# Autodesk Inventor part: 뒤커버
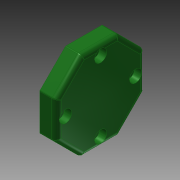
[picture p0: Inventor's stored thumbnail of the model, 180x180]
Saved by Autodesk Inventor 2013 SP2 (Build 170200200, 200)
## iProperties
Created: 2015-11
Part Number: 뒤커버
Material: 알루미늄 6061
Document SubType Name: Modeling
Designer: mduedu
Density: 1 g/cm^3
Author: mduedu
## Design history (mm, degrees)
sketch "스케치5" dims "d66" = 58
  geometry: L1 (12.012, 29)-(29, 12.012); L2 (29, 12.012)-(29, -12.012); L3 (29, -12.012)-(12.012, -29); L4 (12.012, -29)-(-12.012, -29); L5 (-12.012, -29)-(-29, -12.012); L6 (-29, -12.012)-(-29, 12.012); L7 (-29, 12.012)-(-12.012, 29); L8 (-12.012, 29)-(12.012, 29); 4 further points
  constraints: 16 end point, 2 coincident, 2 vertical alignment, 1 midpoint, 19 other
extrude "돌출2" new body sketch "스케치5" distance "d67" = 11; taper "d68" = 0 deg
sketch "스케치6"
  geometry: C1 r 16 at (0, 0); 1 further point
  constraints: 1 centre point, 1 coincident
  dimensions: "d69" = 32 diameter of C1
extrude "돌출3" join sketch "스케치6" distance "d70" = 3; taper "d71" = 0 deg
hole "구멍5" diameter "d74" = 28; stored, may be unused: countersink angle "d78" = 90 deg, drill point angle "d80" = 0 deg; dims "d75" = 6, "d76" = 4, "d77" = 2, "d79" = 10, "d98" = 10, "d99" = 10
fillet "모깎기7" dims "d81" = 1
fillet "모깎기8" dims "d82" = 3
fillet "모깎기9" dims "d83" = 3
fillet "모깎기10" dims "d84" = 0.3
sketch "스케치7" dims "d85" = 46
  geometry: 3 further points
  constraints: 2 vertical alignment, 1 coincident, 2 other
hole "구멍6" sketch "스케치7" at (0, 23) diameter "d86" = 4.5; stored, may be unused: countersink angle "d90" = 90 deg, drill point angle "d92" = 0 deg; dims "d87" = 6, "d88" = 8, "d89" = 4.6, "d91" = 10
node "솔리드2"
pattern_circular "원형 패턴3" dims angle "d94" = 360 deg
